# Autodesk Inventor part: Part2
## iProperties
Created: 2002-07
Part Number: Part2
Document SubType Name: Modeling
Designer: Administrator
Control State: 0
Master: False
Checked Out: False
Shininess: 64.0
Length Units: 11269
Angle Units: 11279
Time Units: 11290
Mass Units: 11283
Length Display Precision: 3
Angle Display Precision: 2
Density: 0.0
Volumn: 0.0
Area: 0.0
PropertySet Name: Model Information
Author: Administrator
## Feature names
1. Extrusion1
2. Extrusion2
